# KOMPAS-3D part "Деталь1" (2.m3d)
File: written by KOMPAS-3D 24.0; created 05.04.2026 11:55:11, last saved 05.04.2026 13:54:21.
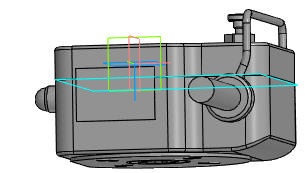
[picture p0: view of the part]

Document properties: Автор: R2D2; Полное имя файла: E:\Работа\Зайцев\Аксессуары для пневмоприводов\Ручной дублер DN.ru\MON4-1200-T54-ISO Ручной дублер DN.ru\исходные материалы\2.m3d

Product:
- Body: Тело 2  | qty 1
    Масса: 29.746799
- Part/product: Деталь1
    Масса: 35.407781
    additional columns: Типовые

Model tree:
1. Операция без истории:1
2. Эскиз:1  (with: Грань.Операция без истории:1, Ребро.Операция без истории:1)
3. Элемент выдавливания:1  (with: Грань.Операция без истории:1)
     Расстояние 1 = -20.8
4. Скругление:1  (with: Ребро.Элемент выдавливания:1)
     Радиус = 3
5. Эскиз:2  (with: Ребро.Скругление:1)
6. Элемент выдавливания:4
     Расстояние 1 = 500
7. Эскиз:3  (with: Грань.Операция без истории:1)
8. Элемент выдавливания:5
     Расстояние 1 = 30.7756
9. Смещенная плоскость:1  (with: Грань.Операция без истории:1)
     Расстояние = 31.2
10. Эскиз:4  (with: Ребро.Операция без истории:1)
11. Элемент выдавливания:6
     Расстояние 2 = 0.5
12. Элемент выдавливания:7  (with: Грань.Операция без истории:1)
     Расстояние 1 = 0.5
